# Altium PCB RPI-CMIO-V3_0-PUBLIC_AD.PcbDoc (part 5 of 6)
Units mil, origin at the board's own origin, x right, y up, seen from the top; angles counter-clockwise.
Board outline 3295.4 x 4105.44 mil, 6 copper layers (TOP, GNDT, PWRT, PWRB, GNDB, BOTTOM); 114 components, 152 nets, 703 pads, 476 vias.
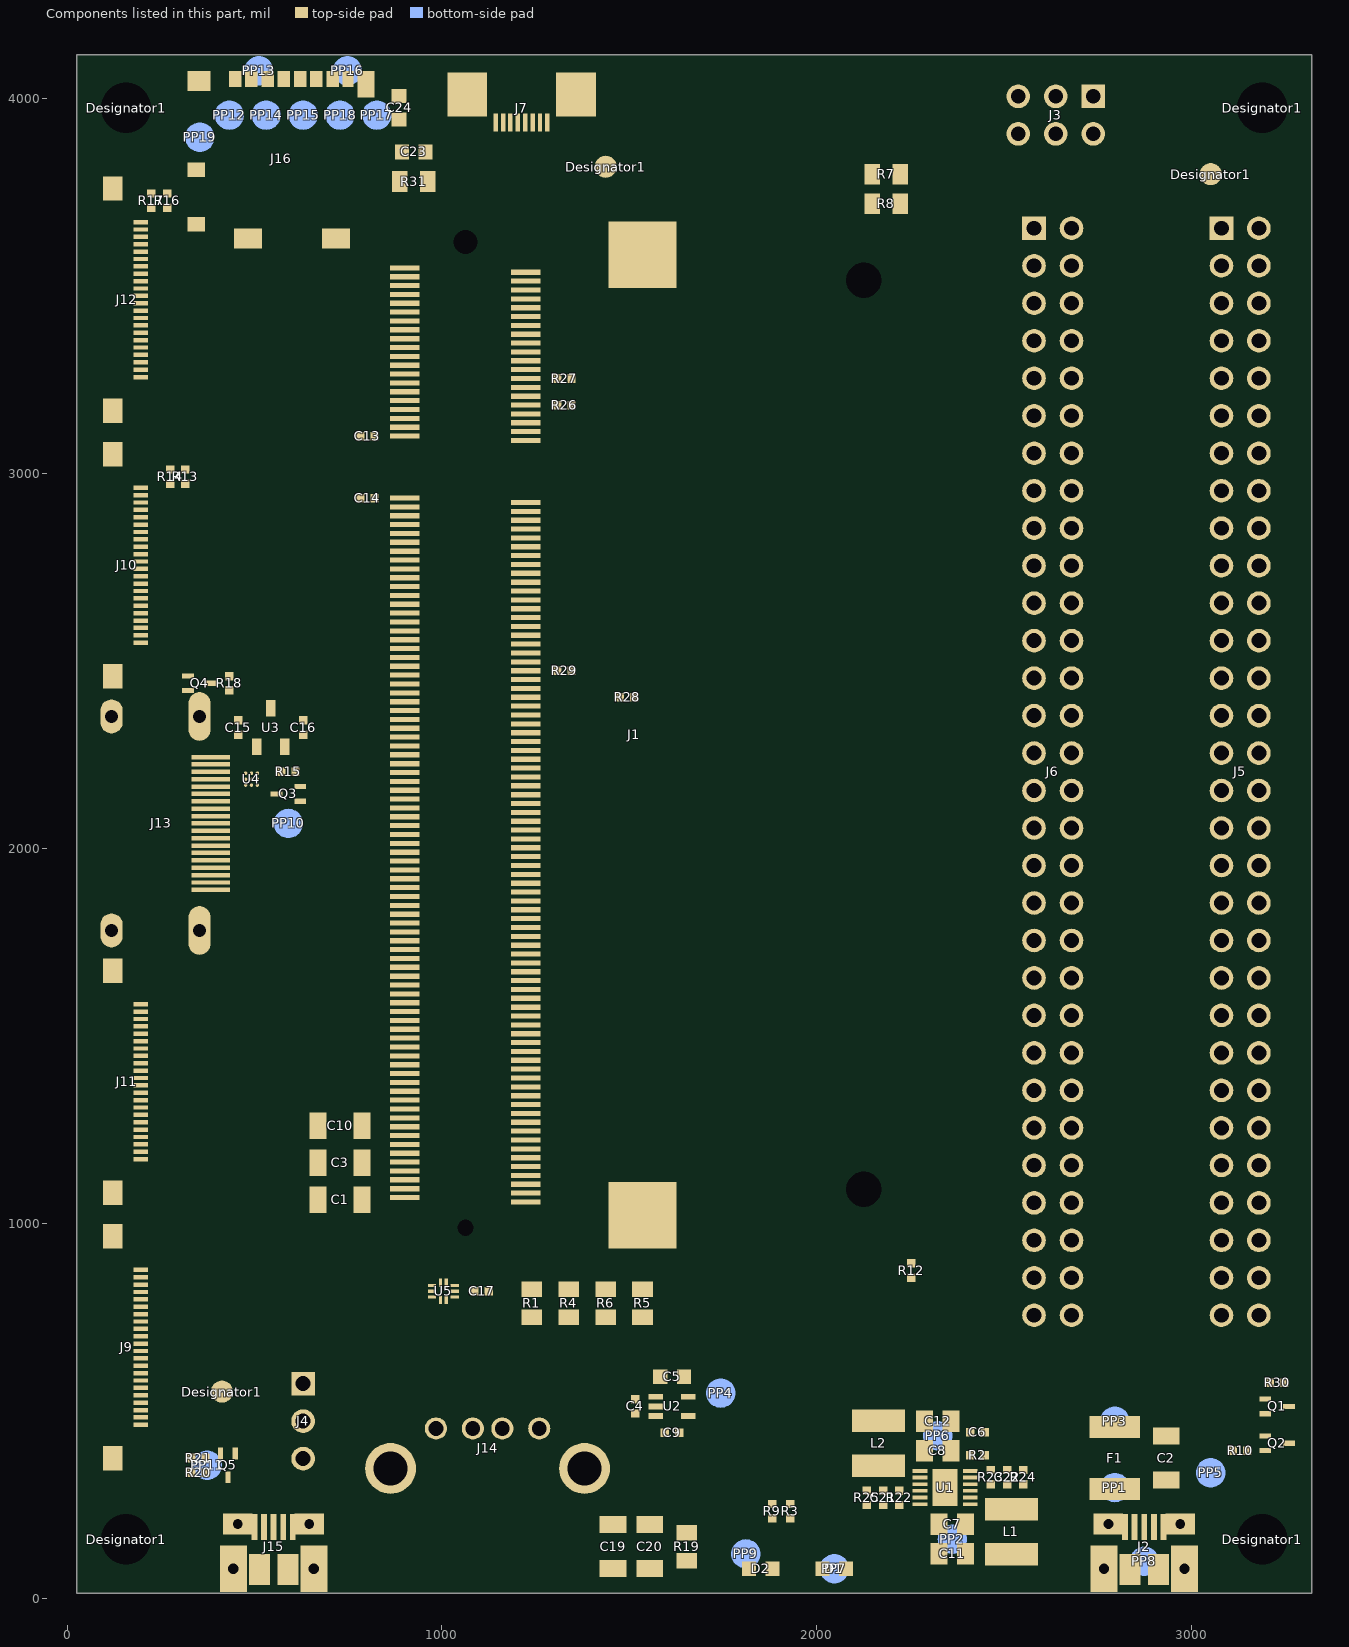
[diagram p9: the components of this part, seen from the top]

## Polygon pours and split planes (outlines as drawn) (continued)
GND on TOP "TOP-GND 73" (solid, pour order 1101): 857.11,3261.57 ccw(c852.93,3265.75) 857.11,3269.92 854.32,3272.71 845.89,3265.75 854.32,3258.79 857.11,3261.57 ccw(c852.93,3265.75)
GND on TOP "TOP-GND 74" (solid, pour order 1102): 857.11,3332.44 ccw(c852.93,3336.61) 857.11,3340.79 854.32,3343.57 845.89,3336.61 854.32,3329.66 857.11,3332.44 ccw(c852.93,3336.61)
GND on TOP "TOP-GND 75" (solid, pour order 1103): 857.11,3403.3 ccw(c852.93,3407.48) 857.11,3411.66 854.32,3414.44 845.89,3407.48 854.32,3400.52 857.11,3403.3 ccw(c852.93,3407.48)
GND on TOP "TOP-GND 76" (solid, pour order 1104): 857.11,3474.17 ccw(c852.93,3478.35) 857.11,3482.52 854.32,3485.3 845.89,3478.35 854.32,3471.39 857.11,3474.17 ccw(c852.93,3478.35)
GND on TOP "TOP-GND 77" (solid, pour order 1105): 1179.94,1100.15 ccw(c1175.76,1104.33) 1179.94,1108.51 1177.15,1111.29 1168.72,1104.33 1177.15,1097.37 1179.94,1100.15 ccw(c1175.76,1104.33)
GND on TOP "TOP-GND 78" (solid, pour order 1106): 1268.88,1273.86 ccw(c1273.05,1269.68) 1268.88,1265.51 1271.66,1262.73 1280.1,1269.68 1271.66,1276.64 1268.88,1273.86 ccw(c1273.05,1269.68)
GND on TOP "TOP-GND 79" (solid, pour order 1107): 1179.94,1194.64 ccw(c1175.76,1198.82) 1179.94,1203 1177.15,1205.78 1168.72,1198.82 1177.15,1191.86 1179.94,1194.64 ccw(c1175.76,1198.82)
GND on TOP "TOP-GND 80" (solid, pour order 1108): 1268.88,1486.46 ccw(c1273.05,1482.28) 1268.88,1478.11 1271.66,1475.33 1280.1,1482.28 1271.66,1489.24 1268.88,1486.46 ccw(c1273.05,1482.28)
GND on TOP "TOP-GND 81" (solid, pour order 1109): 1268.88,1415.59 ccw(c1273.05,1411.42) 1268.88,1407.24 1271.66,1404.46 1280.1,1411.42 1271.66,1418.37 1268.88,1415.59 ccw(c1273.05,1411.42)
GND on TOP "TOP-GND 82" (solid, pour order 1110): 1268.88,1699.06 ccw(c1273.05,1694.88) 1268.88,1690.7 1271.66,1687.93 1280.1,1694.88 1271.66,1701.84 1268.88,1699.06 ccw(c1273.05,1694.88)
GND on TOP "TOP-GND 83" (solid, pour order 1111): 1268.88,1628.19 ccw(c1273.05,1624.02) 1268.88,1619.84 1271.66,1617.06 1280.1,1624.02 1271.66,1630.97 1268.88,1628.19 ccw(c1273.05,1624.02)
GND on TOP "TOP-GND 84" (solid, pour order 1112): 1268.88,1840.79 ccw(c1273.05,1836.61) 1268.88,1832.44 1271.66,1829.66 1280.1,1836.61 1271.66,1843.57 1268.88,1840.79 ccw(c1273.05,1836.61)
GND on TOP "TOP-GND 85" (solid, pour order 1113): 1268.88,1769.93 ccw(c1273.05,1765.75) 1268.88,1761.57 1271.66,1758.79 1280.1,1765.75 1271.66,1772.7 1268.88,1769.93 ccw(c1273.05,1765.75)
GND on TOP "TOP-GND 86" (solid, pour order 1114): 1268.88,2053.39 ccw(c1273.05,2049.21) 1268.88,2045.03 1271.66,2042.26 1280.1,2049.21 1271.66,2056.17 1268.88,2053.39 ccw(c1273.05,2049.21)
GND on TOP "TOP-GND 87" (solid, pour order 1115): 1268.88,1982.52 ccw(c1273.05,1978.35) 1268.88,1974.17 1271.66,1971.39 1280.1,1978.35 1271.66,1985.3 1268.88,1982.52 ccw(c1273.05,1978.35)
GND on TOP "TOP-GND 88" (solid, pour order 1116): 1268.88,2195.12 ccw(c1273.05,2190.95) 1268.88,2186.77 1271.66,2183.99 1280.1,2190.95 1271.66,2197.9 1268.88,2195.12 ccw(c1273.05,2190.95)
GND on TOP "TOP-GND 89" (solid, pour order 1117): 1268.88,2124.26 ccw(c1273.05,2120.08) 1268.88,2115.9 1271.66,2113.12 1280.1,2120.08 1271.66,2127.03 1268.88,2124.26 ccw(c1273.05,2120.08)
GND on TOP "TOP-GND 90" (solid, pour order 1118): 1268.88,2407.72 ccw(c1273.05,2403.54) 1268.88,2399.37 1271.66,2396.59 1280.1,2403.54 1271.66,2410.5 1268.88,2407.72 ccw(c1273.05,2403.54)
GND on TOP "TOP-GND 91" (solid, pour order 1119): 1268.88,2336.85 ccw(c1273.05,2332.68) 1268.88,2328.5 1271.66,2325.72 1280.1,2332.68 1271.66,2339.63 1268.88,2336.85 ccw(c1273.05,2332.68)
GND on TOP "TOP-GND 92" (solid, pour order 1120): 1268.88,2265.99 ccw(c1273.05,2261.81) 1268.88,2257.63 1271.66,2254.85 1280.1,2261.81 1271.66,2268.77 1268.88,2265.99 ccw(c1273.05,2261.81)
GND on TOP "TOP-GND 93" (solid, pour order 1121): 1268.88,2549.45 ccw(c1273.05,2545.28) 1268.88,2541.1 1271.66,2538.32 1280.1,2545.28 1271.66,2552.23 1268.88,2549.45 ccw(c1273.05,2545.28)
GND on TOP "TOP-GND 94" (solid, pour order 1122): 1268.88,2478.59 ccw(c1273.05,2474.41) 1268.88,2470.23 1271.66,2467.45 1280.1,2474.41 1271.66,2481.37 1268.88,2478.59 ccw(c1273.05,2474.41)
GND on TOP "TOP-GND 95" (solid, pour order 1123): 1289.76,2471.63 ccw(c1286.97,2474.41) 1289.76,2477.19 1285.58,2481.37 1277.64,2474.41 1285.58,2467.45 1289.76,2471.63 ccw(c1286.97,2474.41)
GND on TOP "TOP-GND 96" (solid, pour order 1124): 1268.88,2620.32 ccw(c1273.05,2616.14) 1268.88,2611.97 1271.66,2609.18 1280.1,2616.14 1271.66,2623.1 1268.88,2620.32 ccw(c1273.05,2616.14)
GND on TOP "TOP-GND 97" (solid, pour order 1125): 1268.88,2762.05 ccw(c1273.05,2757.87) 1268.88,2753.7 1271.66,2750.92 1280.1,2757.87 1271.66,2764.83 1268.88,2762.05 ccw(c1273.05,2757.87)
GND on TOP "TOP-GND 98" (solid, pour order 1126): 1268.88,2691.18 ccw(c1273.05,2687.01) 1268.88,2682.83 1271.66,2680.05 1280.1,2687.01 1271.66,2693.97 1268.88,2691.18 ccw(c1273.05,2687.01)
GND on TOP "TOP-GND 99" (solid, pour order 1127): 1268.88,2903.78 ccw(c1273.05,2899.61) 1268.88,2895.43 1271.66,2892.65 1280.1,2899.61 1271.66,2906.56 1268.88,2903.78 ccw(c1273.05,2899.61)
GND on TOP "TOP-GND 100" (solid, pour order 1128): 1268.88,2832.92 ccw(c1273.05,2828.74) 1268.88,2824.56 1271.66,2821.78 1280.1,2828.74 1271.66,2835.7 1268.88,2832.92 ccw(c1273.05,2828.74)
GND on TOP "TOP-GND 101" (solid, pour order 1129): 1268.88,3116.38 ccw(c1273.05,3112.21) 1268.88,3108.03 1271.66,3105.25 1280.1,3112.21 1271.66,3119.16 1268.88,3116.38 ccw(c1273.05,3112.21)
GND on TOP "TOP-GND 102" (solid, pour order 1130): 1268.88,3258.11 ccw(c1273.05,3253.94) 1268.88,3249.76 1271.66,3246.98 1280.1,3253.94 1271.66,3260.89 1268.88,3258.11 ccw(c1273.05,3253.94)
GND on TOP "TOP-GND 103" (solid, pour order 1131): 1268.88,3187.25 ccw(c1273.05,3183.07) 1268.88,3178.89 1271.66,3176.11 1280.1,3183.07 1271.66,3190.03 1268.88,3187.25 ccw(c1273.05,3183.07)
GND on TOP "TOP-GND 104" (solid, pour order 1132): 1289.76,3180.29 ccw(c1286.97,3183.07) 1289.76,3185.85 1285.58,3190.03 1277.64,3183.07 1285.58,3176.11 1289.76,3180.29 ccw(c1286.97,3183.07)
GND on TOP "TOP-GND 105" (solid, pour order 1133): 1595.65,515.99 ccw(c1599.83,511.81) 1595.65,507.63 1598.44,504.85 1606.87,511.81 1598.44,518.77 1595.65,515.99 ccw(c1599.83,511.81)
GND on TOP "TOP-GND 106" (solid, pour order 1134): 1558.88,586.37 ccw(c1554.7,590.55) 1558.88,594.73 1556.09,597.51 1547.66,590.55 1556.09,583.6 1558.88,586.37 ccw(c1554.7,590.55)
GND on TOP "TOP-GND 107" (solid, pour order 1135): 1544.68,2407.48 ccw(c1544.8,2403.55) 1542.02,2400.76 1550.13,2392.65 1558.02,2399.31 1552.79,2407.72 1544.68,2407.48 ccw(c1544.8,2403.55)
GND on TOP "TOP-GND 108" (solid, pour order 1136): 1991.95,74.56 ccw(c1987.77,78.74) 1991.95,82.92 1989.16,85.7 1980.73,78.74 1989.16,71.78 1991.95,74.56 ccw(c1987.77,78.74)
GND on TOP "TOP-GND 109" (solid, pour order 1137): 2136.64,233.89 ccw(c2133.86,231.11) 2131.08,233.89 2126.9,229.72 2133.86,221.77 2140.82,229.72 2136.64,233.89 ccw(c2133.86,231.11)
GND on TOP "TOP-GND 110" (solid, pour order 1138): 2254.75,840.19 ccw(c2251.97,837.41) 2249.18,840.19 2245.01,836.02 2251.97,828.07 2258.93,836.02 2254.75,840.19 ccw(c2251.97,837.41)
GND on TOP "TOP-GND 111" (solid, pour order 1139): 2548.4,356.66 ccw(c2551.18,359.44) 2553.97,356.66 2558.14,360.84 2551.18,368.78 2544.22,360.84 2548.4,356.66 ccw(c2551.18,359.44)
GND on TOP "TOP-GND 112" (solid, pour order 1140): 2444.07,458.83 ccw(c2446.85,461.61) 2449.63,458.83 2453.81,463 2446.85,470.94 2439.89,463 2444.07,458.83 ccw(c2446.85,461.61)
GND on TOP "TOP-GND 113" (solid, pour order 1141): 3216.31,396.48 ccw(c3219.09,393.7) 3216.31,390.92 3220.48,386.74 3228.42,393.7 3220.48,400.66 3216.31,396.48 ccw(c3219.09,393.7)
GND on TOP "TOP-GND 114" (solid, pour order 1142): 2316.93,346.46 2316.93,523.62 2381.89,523.62 2381.89,346.46 2377.95,346.46 2377.95,244.09 2368.11,244.09 2368.11,88.58 2303.15,88.58 2303.15,226.38 2307.09,226.38 2307.09,346.46
GND on TOP "TOP-GND 115" (solid, pour order 1143): 567 vertices, not listed, extent 19.68,19.68 3326.77,4114.17
GND on TOP "TOP-GND 116" (solid, pour order 1144): 1325.91,2410.94 ccw(c1338.59,2401.58) 1322.83,2401.58 1322.83,2399.75 1312.85,2389.77 1269.69,2389.77 1269.69,2417.32 1322.69,2417.32 cw(c1322.69,2413.32) 1325.91,2410.94 ccw(c1338.59,2401.58)
GND on TOP "TOP-GND 117" (solid, pour order 1145): 440.56,2194.89 440.56,2234.24 443.44,2234.24 460.62,2217.06 460.62,2207.55 465.91,2202.26 465.85,2201.37 ccw(c476.38,2200.79) 465.93,2199.41 cw(c461.96,2198.89) 461.97,2194.89
GND on TOP "TOP-GND 118" (solid, pour order 1146): 946.86,1238.74 cw(c950.86,1238.74) 951.85,1242.62 ccw(c955.79,1257.87) 961.37,1243.14 cw(c962.78,1239.4) 966.78,1239.4 966.78,1181.86 cw(c962.78,1181.86) 961.37,1178.12 ccw(c955.79,1163.39) 951.85,1178.64 cw(c950.86,1182.52) 946.86,1182.52 946.86,1238.74 cw(c950.86,1238.74)
GND on TOP "TOP-GND 119" (solid, pour order 1147): 946.86,1144.26 cw(c950.86,1144.26) 951.85,1148.13 ccw(c955.79,1163.39) 961.37,1148.65 cw(c962.78,1144.91) 966.78,1144.91 966.78,1087.37 cw(c962.78,1087.37) 961.37,1083.63 ccw(c955.79,1068.9) 951.85,1084.15 cw(c950.86,1088.03) 946.86,1088.03 946.86,1144.26 cw(c950.86,1144.26)
GPIO7 on TOP "TOP-GPIO7" (solid, pour order 1148): 961.31,3292.15 ccw(c964.09,3289.37) 961.31,3286.59 965.48,3282.41 973.42,3289.37 965.48,3296.33 961.31,3292.15 ccw(c964.09,3289.37)
1V8 on TOP "TOP-1V8" (solid, pour order 1149): 397.64,2470.2 ccw(c397.64,2474.13) 401.58,2474.13 401.58,2480.04 391.04,2480.74 391.73,2470.2 397.64,2470.2 ccw(c397.64,2474.13)
1V8 on TOP "TOP-1V8 1" (solid, pour order 1150): 2297.24,519.76 ccw(c2291.34,519.76) 2291.34,525.67 2287.4,525.67 2286.36,514.78 2297.24,515.83 2297.24,519.76 ccw(c2291.34,519.76)
1V8 on TOP "TOP-1V8 2" (solid, pour order 1151): 3151.6,377.79 ccw(c3148.82,375) 3146.04,377.79 3141.86,373.61 3148.82,365.67 3155.78,373.61 3151.6,377.79 ccw(c3148.82,375)
GPIO26 on TOP "TOP-GPIO26" (solid, pour order 1152): 1105.01,2394.52 ccw(c1107.79,2391.73) 1105.01,2388.95 1109.18,2384.78 1117.13,2391.73 1109.18,2398.69 1105.01,2394.52 ccw(c1107.79,2391.73)
3V3 on TOP "TOP-3V3" (solid, pour order 1153): 173.46,873.2 ccw(c170.67,875.98) 173.46,878.77 169.28,882.94 161.34,875.98 169.28,869.03 173.46,873.2 ccw(c170.67,875.98)
3V3 on TOP "TOP-3V3 1" (solid, pour order 1154): 220.24,1587.43 ccw(c223.03,1584.65) 220.24,1581.86 224.42,1577.69 232.36,1584.65 224.42,1591.6 220.24,1587.43 ccw(c223.03,1584.65)
3V3 on TOP "TOP-3V3 2" (solid, pour order 1155): 173.46,2959.82 ccw(c170.67,2962.6) 173.46,2965.38 169.28,2969.55 161.34,2962.6 169.28,2955.64 173.46,2959.82 ccw(c170.67,2962.6)
3V3 on TOP "TOP-3V3 3" (solid, pour order 1156): 173.46,3668.48 ccw(c170.67,3671.26) 173.46,3674.04 169.28,3678.22 161.34,3671.26 169.28,3664.3 173.46,3668.48 ccw(c170.67,3671.26)
3V3 on TOP "TOP-3V3 4" (solid, pour order 1157): 316.57,331.86 ccw(c313.78,334.65) 316.57,337.43 312.39,341.6 304.45,334.65 312.39,327.69 316.57,331.86 ccw(c313.78,334.65)
3V3 on TOP "TOP-3V3 5" (solid, pour order 1158): 272.81,3025.95 ccw(c275.59,3028.74) 278.37,3025.95 282.55,3030.13 275.59,3038.07 268.63,3030.13 272.81,3025.95 ccw(c275.59,3028.74)
3V3 on TOP "TOP-3V3 6" (solid, pour order 1159): 312.18,3026.27 ccw(c314.96,3029.05) 317.74,3026.27 321.92,3030.44 314.96,3038.39 308,3030.44 312.18,3026.27 ccw(c314.96,3029.05)
3V3 on TOP "TOP-3V3 7" (solid, pour order 1160): 624.38,2207.51 ccw(c627.16,2204.72) 624.38,2201.94 628.55,2197.77 636.5,2204.72 628.55,2211.68 624.38,2207.51 ccw(c627.16,2204.72)
3V3 on TOP "TOP-3V3 8" (solid, pour order 1161): 1091.37,802.08 ccw(c1088.58,799.3) 1085.8,802.08 1081.63,797.9 1088.58,789.96 1095.54,797.9 1091.37,802.08 ccw(c1088.58,799.3)
3V3 on TOP "TOP-3V3 9" (solid, pour order 1162): 1595.65,490.4 ccw(c1599.83,486.22) 1595.65,482.04 1598.44,479.26 1606.87,486.22 1598.44,493.18 1595.65,490.4 ccw(c1599.83,486.22)
3V3 on TOP "TOP-3V3 10" (solid, pour order 1163): 1595.65,541.58 ccw(c1599.83,537.4) 1595.65,533.22 1598.44,530.44 1606.87,537.4 1598.44,544.36 1595.65,541.58 ccw(c1599.83,537.4)
3V3 on TOP "TOP-3V3 11" (solid, pour order 1164): 1877.71,265.85 ccw(c1881.89,270.02) 1886.07,265.85 1888.85,268.63 1881.89,277.07 1874.93,268.63 1877.71,265.85 ccw(c1881.89,270.02)
3V3 on TOP "TOP-3V3 12" (solid, pour order 1165): 1924.96,265.85 ccw(c1929.13,270.02) 1933.31,265.85 1936.09,268.63 1929.13,277.07 1922.18,268.63 1924.96,265.85 ccw(c1929.13,270.02)
3V3 on TOP "TOP-3V3 13" (solid, pour order 1166): 2387.89,78.9 ccw(c2392.07,74.72) 2387.89,70.55 2390.68,67.77 2399.11,74.72 2390.68,81.68 2387.89,78.9 ccw(c2392.07,74.72)
GPIO4 on TOP "TOP-GPIO4" (solid, pour order 1167): 980.99,3386.64 ccw(c983.78,3383.86) 980.99,3381.08 985.16,3376.9 993.11,3383.86 985.16,3390.82 980.99,3386.64 ccw(c983.78,3383.86)
GPIO24 on TOP "TOP-GPIO24" (solid, pour order 1168): 1126.66,2465.38 ccw(c1129.45,2462.6) 1126.66,2459.82 1130.84,2455.64 1138.78,2462.6 1130.84,2469.55 1126.66,2465.38 ccw(c1129.45,2462.6)
GPIO28-45_VREF on TOP "TOP-GPIO28-45_VREF" (solid, pour order 1169): 946.04,2939.22 ccw(c950.22,2935.04) 946.04,2930.86 948.83,2928.08 957.26,2935.04 948.83,2942 946.04,2939.22 ccw(c950.22,2935.04)
GPIO28-45_VREF on TOP "TOP-GPIO28-45_VREF 1" (solid, pour order 1170): 1179.94,2919.05 ccw(c1175.76,2923.23) 1179.94,2927.41 1177.15,2930.18 1168.72,2923.23 1177.15,2916.27 1179.94,2919.05 ccw(c1175.76,2923.23)
VC_TRST_N on TOP "TOP-VC_TRST_N" (solid, pour order 1171): 1504.61,1390.58 ccw(c1507.4,1387.8) 1504.61,1385.01 1508.79,1380.84 1516.73,1387.8 1508.79,1394.75 1504.61,1390.58 ccw(c1507.4,1387.8)
CAM0_CN on TOP "TOP-CAM0_CN" (solid, pour order 1172): 147.79,592.54 ccw(c146.17,594.15) 147.79,595.77 142.44,601.11 134.91,594.15 142.44,587.2 147.79,592.54 ccw(c146.17,594.15)
CAM0_CN on TOP "TOP-CAM0_CN 1" (solid, pour order 1173): 1313.9,1724.63 ccw(c1313.9,1722.35) 1311.61,1722.35 1311.61,1714.79 1321.86,1714.39 1321.46,1724.63 1313.9,1724.63 ccw(c1313.9,1722.35)
GPIO2 on TOP "TOP-GPIO2" (solid, pour order 1174): 944.65,3457.51 ccw(c947.44,3454.72) 944.65,3451.94 948.83,3447.77 956.77,3454.72 948.83,3461.68 944.65,3457.51 ccw(c947.44,3454.72)
DSI1_DN3 on TOP "TOP-DSI1_DN3" (solid, pour order 1175): 252.82,3518.63 ccw(c252.82,3516.35) 250.54,3516.35 250.54,3508.79 260.78,3508.39 260.38,3518.63 252.82,3518.63 ccw(c252.82,3516.35)
DSI1_DN3 on TOP "TOP-DSI1_DN3 1" (solid, pour order 1176): 1313.64,2149.85 ccw(c1313.64,2147.59) 1311.38,2147.59 1311.38,2140.01 1321.62,2139.61 1321.22,2149.85 1313.64,2149.85 ccw(c1313.64,2147.59)
GPIO20 on TOP "TOP-GPIO20" (solid, pour order 1177): 967.21,2607.11 ccw(c970,2604.33) 967.21,2601.55 971.39,2597.37 979.33,2604.33 971.39,2611.29 967.21,2607.11 ccw(c970,2604.33)
GPIO8 on TOP "TOP-GPIO8" (solid, pour order 1178): 975.09,3244.91 ccw(c977.87,3242.13) 975.09,3239.34 979.26,3235.17 987.21,3242.13 979.26,3249.08 975.09,3244.91 ccw(c977.87,3242.13)
DSI1_DN2 on TOP "TOP-DSI1_DN2" (solid, pour order 1179): 266.76,3457.85 ccw(c266.76,3455.57) 264.48,3455.57 264.48,3448.01 274.72,3447.61 274.32,3457.85 266.76,3457.85 ccw(c266.76,3455.57)
DSI1_DN2 on TOP "TOP-DSI1_DN2 1" (solid, pour order 1180): 1313.68,2078.84 ccw(c1313.68,2076.58) 1311.42,2076.58 1311.42,2069 1321.66,2068.6 1321.26,2078.84 1313.68,2078.84 ccw(c1313.68,2076.58)
DSI0_DP1 on TOP "TOP-DSI0_DP1" (solid, pour order 1181): 289.45,2511.87 ccw(c287.84,2510.25) 286.22,2511.87 280.88,2506.52 287.84,2498.99 294.8,2506.52 289.45,2511.87 ccw(c287.84,2510.25)
DSI0_DP1 on TOP "TOP-DSI0_DP1 1" (solid, pour order 1182): 750,2300.06 ccw(c747.72,2300.06) 747.72,2302.34 740.16,2302.34 739.75,2292.1 750,2292.5 750,2300.06 ccw(c747.72,2300.06)
VC_TDO on TOP "TOP-VC_TDO" (solid, pour order 1183): 1453.43,1319.71 ccw(c1456.22,1316.93) 1453.43,1314.15 1457.61,1309.97 1465.55,1316.93 1457.61,1323.89 1453.43,1319.71 ccw(c1456.22,1316.93)
GPIO15 on TOP "TOP-GPIO15" (solid, pour order 1184): 951.47,2796.09 ccw(c954.25,2793.31) 951.47,2790.52 955.64,2786.35 963.58,2793.31 955.64,2800.26 951.47,2796.09 ccw(c954.25,2793.31)
GPIO25 on TOP "TOP-GPIO25" (solid, pour order 1185): 1097.13,2441.76 ccw(c1099.92,2438.98) 1097.13,2436.19 1101.31,2432.02 1109.25,2438.98 1101.31,2445.93 1097.13,2441.76 ccw(c1099.92,2438.98)
DSI1_DN0 on TOP "TOP-DSI1_DN0" (solid, pour order 1186): 590.87,3280.69 ccw(c590.87,3278.41) 588.58,3278.41 588.58,3270.85 598.83,3270.44 598.42,3280.69 590.87,3280.69 ccw(c590.87,3278.41)
DSI1_DN0 on TOP "TOP-DSI1_DN0 1" (solid, pour order 1187): 1313.64,2291.59 ccw(c1313.64,2289.32) 1311.38,2289.32 1311.38,2281.74 1321.62,2281.34 1321.22,2291.59 1313.64,2291.59 ccw(c1313.64,2289.32)
GPIO17 on TOP "TOP-GPIO17" (solid, pour order 1188): 944.65,2725.22 ccw(c947.44,2722.44) 944.65,2719.66 948.83,2715.48 956.77,2722.44 948.83,2729.4 944.65,2725.22 ccw(c947.44,2722.44)
GPIO11 on TOP "TOP-GPIO11" (solid, pour order 1189): 944.65,3150.42 ccw(c947.44,3147.64) 944.65,3144.85 948.83,3140.68 956.77,3147.64 948.83,3154.59 944.65,3150.42 ccw(c947.44,3147.64)
GPIO22 on TOP "TOP-GPIO22" (solid, pour order 1190): 1022.33,2536.25 ccw(c1025.11,2533.47) 1022.33,2530.68 1026.5,2526.51 1034.45,2533.47 1026.5,2540.42 1022.33,2536.25 ccw(c1025.11,2533.47)
CD1_SCL on TOP "TOP-CD1_SCL" (solid, pour order 1191): 174.52,1542.49 ccw(c171.74,1545.28) 174.52,1548.06 170.35,1552.23 162.4,1545.28 170.35,1538.32 174.52,1542.49 ccw(c171.74,1545.28)
CD1_SCL on TOP "TOP-CD1_SCL 1" (solid, pour order 1192): 173.46,3629.11 ccw(c170.67,3631.89) 173.46,3634.67 169.28,3638.85 161.34,3631.89 169.28,3624.93 173.46,3629.11 ccw(c170.67,3631.89)
HDMI_CEC on TOP "TOP-HDMI_CEC" (solid, pour order 1193): 648.32,2168.14 ccw(c651.1,2165.35) 648.32,2162.57 652.49,2158.4 660.43,2165.35 652.49,2172.31 648.32,2168.14 ccw(c651.1,2165.35)
HDMI_CEC on TOP "TOP-HDMI_CEC 1" (solid, pour order 1194): 822.16,1396.82 ccw(c819.37,1399.61) 822.16,1402.39 817.98,1406.56 810.04,1399.61 817.98,1392.65 822.16,1396.82 ccw(c819.37,1399.61)
CAM1_IO0 on TOP "TOP-CAM1_IO0" (solid, pour order 1195): 250.68,1489 ccw(c253.46,1486.22) 250.68,1483.44 254.85,1479.26 262.8,1486.22 254.85,1493.18 250.68,1489 ccw(c253.46,1486.22)
CD1_SDA on TOP "TOP-CD1_SDA" (solid, pour order 1196): 144.99,1562.18 ccw(c142.21,1564.96) 144.99,1567.74 140.82,1571.92 132.87,1564.96 140.82,1558 144.99,1562.18 ccw(c142.21,1564.96)
CD1_SDA on TOP "TOP-CD1_SDA 1" (solid, pour order 1197): 150.9,3648.79 ccw(c148.11,3651.58) 150.9,3654.36 146.72,3658.53 138.78,3651.58 146.72,3644.62 150.9,3648.79 ccw(c148.11,3651.58)
DSI1_CP on TOP "TOP-DSI1_CP" (solid, pour order 1198): 496.06,3414.51 ccw(c498.35,3414.51) 498.35,3412.22 505.91,3412.22 506.31,3422.47 496.06,3422.07 496.06,3414.51 ccw(c498.35,3414.51)
DSI1_CP on TOP "TOP-DSI1_CP 1" (solid, pour order 1199): 1311.42,2234.15 ccw(c1313.68,2234.15) 1313.68,2231.89 1321.26,2231.89 1321.66,2242.13 1311.42,2241.73 1311.42,2234.15 ccw(c1313.68,2234.15)
CAM1_IO1 on TOP "TOP-CAM1_IO1" (solid, pour order 1200): 170.58,1503.12 ccw(c167.8,1505.91) 170.58,1508.69 166.41,1512.86 158.47,1505.91 166.41,1498.95 170.58,1503.12 ccw(c167.8,1505.91)
VDD_CORE on TOP "TOP-VDD_CORE" (solid, pour order 1201): 960.63,1301.18 ccw(c960.63,1297.24) 956.69,1297.24 956.69,1291.34 967.23,1290.64 966.54,1301.18 960.63,1301.18 ccw(c960.63,1297.24)
VDD_CORE on TOP "TOP-VDD_CORE 1" (solid, pour order 1202): 2044.6,1302.34 ccw(c2041.82,1305.12) 2044.6,1307.9 2040.43,1312.08 2032.48,1305.12 2040.43,1298.16 2044.6,1302.34 ccw(c2041.82,1305.12)
GPIO16 on TOP "TOP-GPIO16" (solid, pour order 1203): 973.12,2748.85 ccw(c975.9,2746.06) 973.12,2743.28 977.29,2739.11 985.24,2746.06 977.29,2753.02 973.12,2748.85 ccw(c975.9,2746.06)
DSI0_CP on TOP "TOP-DSI0_CP" (solid, pour order 1204): 127.91,2703.56 ccw(c127.91,2705.85) 130.19,2705.85 130.19,2713.41 119.94,2713.81 120.35,2703.56 127.91,2703.56 ccw(c127.91,2705.85)
DSI0_CP on TOP "TOP-DSI0_CP 1" (solid, pour order 1205): 689.87,2392.66 ccw(c691.49,2394.28) 693.1,2392.66 698.44,2398.01 691.49,2405.54 684.53,2398.01 689.87,2392.66 ccw(c691.49,2394.28)
GPIO14 on TOP "TOP-GPIO14" (solid, pour order 1206): 975.09,2819.71 ccw(c977.87,2816.93) 975.09,2814.15 979.26,2809.97 987.21,2816.93 979.26,2823.89 975.09,2819.71 ccw(c977.87,2816.93)
RUN on TOP "TOP-RUN" (solid, pour order 1207): 944.65,1331.52 ccw(c947.44,1328.74) 944.65,1325.96 948.83,1321.78 956.77,1328.74 948.83,1335.7 944.65,1331.52 ccw(c947.44,1328.74)
VC_TMS on TOP "TOP-VC_TMS" (solid, pour order 1208): 1421.94,1343.34 ccw(c1424.72,1340.55) 1421.94,1337.77 1426.11,1333.59 1434.05,1340.55 1426.11,1347.51 1421.94,1343.34 ccw(c1424.72,1340.55)
VC_TCK on TOP "TOP-VC_TCK" (solid, pour order 1209): 1396.49,1296.09 ccw(c1399.27,1293.31) 1396.49,1290.52 1400.66,1286.35 1408.61,1293.31 1400.66,1300.26 1396.49,1296.09 ccw(c1399.27,1293.31)
VC_TDI on TOP "TOP-VC_TDI" (solid, pour order 1210): 1480.99,1366.96 ccw(c1483.78,1364.17) 1480.99,1361.39 1485.16,1357.22 1493.11,1364.17 1485.16,1371.13 1480.99,1366.96 ccw(c1483.78,1364.17)
DSI1_DP1 on TOP "TOP-DSI1_DP1" (solid, pour order 1211): 264.48,3355.45 ccw(c266.76,3355.45) 266.76,3353.17 274.32,3353.17 274.72,3363.42 264.48,3363.01 264.48,3355.45 ccw(c266.76,3355.45)
DSI1_DP1 on TOP "TOP-DSI1_DP1 1" (solid, pour order 1212): 1311.38,2021.7 ccw(c1313.64,2021.7) 1313.64,2019.44 1321.22,2019.44 1321.62,2029.68 1311.38,2029.28 1311.38,2021.7 ccw(c1313.64,2021.7)
DSI1_DP3 on TOP "TOP-DSI1_DP3" (solid, pour order 1213): 250.54,3534.35 ccw(c252.82,3534.35) 252.82,3532.06 260.38,3532.06 260.78,3542.31 250.54,3541.91 250.54,3534.35 ccw(c252.82,3534.35)
DSI1_DP3 on TOP "TOP-DSI1_DP3 1" (solid, pour order 1214): 1311.38,2163.43 ccw(c1313.64,2163.43) 1313.64,2161.17 1321.22,2161.17 1321.62,2171.41 1311.38,2171.01 1311.38,2163.43 ccw(c1313.64,2163.43)
GPIO9 on TOP "TOP-GPIO9" (solid, pour order 1215): 951.47,3221.29 ccw(c954.25,3218.5) 951.47,3215.72 955.64,3211.55 963.58,3218.5 955.64,3225.46 951.47,3221.29 ccw(c954.25,3218.5)
CAM0_CP on TOP "TOP-CAM0_CP" (solid, pour order 1216): 147.79,623.58 ccw(c146.17,625.2) 147.79,626.81 142.44,632.15 134.91,625.2 142.44,618.24 147.79,623.58 ccw(c146.17,625.2)
CAM0_CP on TOP "TOP-CAM0_CP 1" (solid, pour order 1217): 1311.61,1738.28 ccw(c1313.9,1738.28) 1313.9,1735.99 1321.46,1735.99 1321.86,1746.24 1311.61,1745.84 1311.61,1738.28 ccw(c1313.9,1738.28)
GPIO0 on TOP "TOP-GPIO0" (solid, pour order 1218): 944.65,3528.37 ccw(c947.44,3525.59) 944.65,3522.81 948.83,3518.63 956.77,3525.59 948.83,3532.55 944.65,3528.37 ccw(c947.44,3525.59)
GPIO3 on TOP "TOP-GPIO3" (solid, pour order 1219): 965.24,3433.89 ccw(c968.03,3431.1) 965.24,3428.32 969.42,3424.15 977.36,3431.1 969.42,3438.06 965.24,3433.89 ccw(c968.03,3431.1)
GPIO1 on TOP "TOP-GPIO1" (solid, pour order 1220): 965.24,3504.75 ccw(c968.03,3501.97) 965.24,3499.18 969.42,3495.01 977.36,3501.97 969.42,3508.92 965.24,3504.75 ccw(c968.03,3501.97)
CEC on TOP "TOP-CEC" (solid, pour order 1221): 328.58,2123.2 ccw(c325.79,2125.98) 328.58,2128.77 324.4,2132.94 316.46,2125.98 324.4,2119.03 328.58,2123.2 ccw(c325.79,2125.98)
CAM0_DN1 on TOP "TOP-CAM0_DN1" (solid, pour order 1222): 147.79,533.48 ccw(c146.17,535.1) 147.79,536.71 142.44,542.06 134.91,535.1 142.44,528.14 147.79,533.48 ccw(c146.17,535.1)
CAM0_DN1 on TOP "TOP-CAM0_DN1 1" (solid, pour order 1223): 1313.9,1653.77 ccw(c1313.9,1651.48) 1311.61,1651.48 1311.61,1643.93 1321.86,1643.52 1321.46,1653.77 1313.9,1653.77 ccw(c1313.9,1651.48)
H5V on TOP "TOP-H5V" (solid, pour order 1224): 602.59,2123.2 ccw(c599.81,2125.98) 602.59,2128.77 598.42,2132.94 590.47,2125.98 598.42,2119.03 602.59,2123.2 ccw(c599.81,2125.98)
H5V on TOP "TOP-H5V 1" (solid, pour order 1225): 517.1,2203.57 ccw(c519.88,2200.79) 517.1,2198 521.27,2193.83 529.21,2200.79 521.27,2207.74 517.1,2203.57 ccw(c519.88,2200.79)
H5V on TOP "TOP-H5V 2" (solid, pour order 1226): 538.07,2204.72 ccw(c532.16,2204.72) 532.16,2210.63 528.23,2210.63 527.18,2199.74 538.07,2200.79 538.07,2204.72 ccw(c532.16,2204.72)
H5V on TOP "TOP-H5V 3" (solid, pour order 1227): 517.1,2172.08 ccw(c519.88,2169.29) 517.1,2166.51 521.27,2162.34 529.21,2169.29 521.27,2176.25 517.1,2172.08 ccw(c519.88,2169.29)
DSI1_CN on TOP "TOP-DSI1_CN" (solid, pour order 1228): 498.35,3398.79 ccw(c498.35,3396.51) 496.06,3396.51 496.06,3388.95 506.31,3388.55 505.91,3398.79 498.35,3398.79 ccw(c498.35,3396.51)
DSI1_CN on TOP "TOP-DSI1_CN 1" (solid, pour order 1229): 1313.68,2220.58 ccw(c1313.68,2218.31) 1311.42,2218.31 1311.42,2210.73 1321.66,2210.33 1321.26,2220.58 1313.68,2220.58 ccw(c1313.68,2218.31)
GPIO18 on TOP "TOP-GPIO18" (solid, pour order 1230): 975.09,2677.98 ccw(c977.87,2675.2) 975.09,2672.41 979.26,2668.24 987.21,2675.2 979.26,2682.15 975.09,2677.98 ccw(c977.87,2675.2)
DSI1_DP2 on TOP "TOP-DSI1_DP2" (solid, pour order 1231): 264.48,3473.57 ccw(c266.76,3473.57) 266.76,3471.28 274.32,3471.28 274.72,3481.53 264.48,3481.13 264.48,3473.57 ccw(c266.76,3473.57)
DSI1_DP2 on TOP "TOP-DSI1_DP2 1" (solid, pour order 1232): 1311.42,2092.42 ccw(c1313.68,2092.42) 1313.68,2090.16 1321.26,2090.16 1321.66,2100.4 1311.42,2100 1311.42,2092.42 ccw(c1313.68,2092.42)
DSI0_CN on TOP "TOP-DSI0_CN" (solid, pour order 1233): 130.19,2687.85 ccw(c127.91,2687.85) 127.91,2690.13 120.35,2690.13 119.94,2679.89 130.19,2680.29 130.19,2687.85 ccw(c127.91,2687.85)
DSI0_CN on TOP "TOP-DSI0_CN 1" (solid, pour order 1234): 702.6,2383.16 ccw(c704.22,2381.55) 702.6,2379.94 707.94,2374.6 715.48,2381.55 707.94,2388.51 702.6,2383.16 ccw(c704.22,2381.55)
GPIO21 on TOP "TOP-GPIO21" (solid, pour order 1235): 944.65,2583.49 ccw(c947.44,2580.71) 944.65,2577.93 948.83,2573.75 956.77,2580.71 948.83,2587.66 944.65,2583.49 ccw(c947.44,2580.71)
USB_OTGID on TOP "TOP-USB_OTGID" (solid, pour order 1236): 1564.96,1399.61 ccw(c1564.96,1395.67) 1561.02,1395.67 1561.02,1389.76 1571.56,1389.07 1570.87,1399.61 1564.96,1399.61 ccw(c1564.96,1395.67)
USB_OTGID on TOP "TOP-USB_OTGID 1" (solid, pour order 1237): 2187.01,1253.94 ccw(c2187.01,1257.87) 2190.95,1257.87 2190.95,1263.78 2180.41,1264.48 2181.1,1253.94 2187.01,1253.94 ccw(c2187.01,1257.87)
GPIO13 on TOP "TOP-GPIO13" (solid, pour order 1238): 951.47,2866.96 ccw(c954.25,2864.17) 951.47,2861.39 955.64,2857.22 963.58,2864.17 955.64,2871.13 951.47,2866.96 ccw(c954.25,2864.17)
CAM0_DP0 on TOP "TOP-CAM0_DP0" (solid, pour order 1239): 264.97,688.48 ccw(c266.58,690.1) 268.2,688.48 273.54,693.83 266.58,701.36 259.63,693.83 264.97,688.48 ccw(c266.58,690.1)
CAM0_DP0 on TOP "TOP-CAM0_DP0 1" (solid, pour order 1240): 1311.42,1807.4 ccw(c1313.7,1807.4) 1313.7,1805.12 1321.26,1805.12 1321.66,1815.37 1311.42,1814.96 1311.42,1807.4 ccw(c1313.7,1807.4)
GPIO0-27_VREF on TOP "TOP-GPIO0-27_VREF" (solid, pour order 1241): 946.04,3104.57 ccw(c950.22,3100.39) 946.04,3096.22 948.83,3093.44 957.26,3100.39 948.83,3107.35 946.04,3104.57 ccw(c950.22,3100.39)
GPIO0-27_VREF on TOP "TOP-GPIO0-27_VREF 1" (solid, pour order 1242): 1179.94,3084.41 ccw(c1175.76,3088.58) 1179.94,3092.76 1177.15,3095.54 1168.72,3088.58 1177.15,3081.63 1179.94,3084.41 ccw(c1175.76,3088.58)
GPIO10 on TOP "TOP-GPIO10" (solid, pour order 1243): 975.09,3174.04 ccw(c977.87,3171.26) 975.09,3168.48 979.26,3164.3 987.21,3171.26 979.26,3178.22 975.09,3174.04 ccw(c977.87,3171.26)
TVDAC on TOP "TOP-TVDAC" (solid, pour order 1244): 2537.12,756.47 ccw(c2538.86,754.72) 2537.12,752.98 2557.65,732.46 2580.53,754.72 2557.65,776.99 2537.12,756.47 ccw(c2538.86,754.72)
CM_VBAT on TOP "TOP-CM_VBAT" (solid, pour order 1245): 857.11,1088.34 ccw(c852.93,1092.52) 857.11,1096.7 854.32,1099.48 845.89,1092.52 854.32,1085.56 857.11,1088.34 ccw(c852.93,1092.52)
CM_VBAT on TOP "TOP-CM_VBAT 1" (solid, pour order 1246): 837.62,1096.7 ccw(c841.8,1092.52) 837.62,1088.34 840.4,1085.56 848.84,1092.52 840.4,1099.48 837.62,1096.7 ccw(c841.8,1092.52)
CM_VBAT on TOP "TOP-CM_VBAT 2" (solid, pour order 1247): 946.04,1073.08 ccw(c950.22,1068.9) 946.04,1064.72 948.83,1061.94 957.26,1068.9 948.83,1075.85 946.04,1073.08 ccw(c950.22,1068.9)
CM_VBAT on TOP "TOP-CM_VBAT 3" (solid, pour order 1248): 1268.88,1084.89 ccw(c1273.05,1080.71) 1268.88,1076.53 1271.66,1073.75 1280.1,1080.71 1271.66,1087.66 1268.88,1084.89 ccw(c1273.05,1080.71)
CM_VBAT on TOP "TOP-CM_VBAT 4" (solid, pour order 1249): 1179.94,1052.91 ccw(c1175.76,1057.09) 1179.94,1061.26 1177.15,1064.04 1168.72,1057.09 1177.15,1050.13 1179.94,1052.91 ccw(c1175.76,1057.09)
GPIO5 on TOP "TOP-GPIO5" (solid, pour order 1250): 959.34,3363.02 ccw(c962.12,3360.24) 959.34,3357.45 963.51,3353.28 971.46,3360.24 963.51,3367.19 959.34,3363.02 ccw(c962.12,3360.24)
CM_1V8 on TOP "TOP-CM_1V8" (solid, pour order 1251): 857.11,1230.08 ccw(c852.93,1234.25) 857.11,1238.43 854.32,1241.21 845.89,1234.25 854.32,1227.3 857.11,1230.08 ccw(c852.93,1234.25)
CM_1V8 on TOP "TOP-CM_1V8 1" (solid, pour order 1252): 837.62,1238.43 ccw(c841.8,1234.25) 837.62,1230.08 840.4,1227.3 848.84,1234.25 840.4,1241.21 837.62,1238.43 ccw(c841.8,1234.25)
CM_1V8 on TOP "TOP-CM_1V8 2" (solid, pour order 1253): 946.04,1262.05 ccw(c950.22,1257.87) 946.04,1253.7 948.83,1250.92 957.26,1257.87 948.83,1264.83 946.04,1262.05 ccw(c950.22,1257.87)
CM_1V8 on TOP "TOP-CM_1V8 3" (solid, pour order 1254): 1179.94,1241.89 ccw(c1175.76,1246.06) 1179.94,1250.24 1177.15,1253.02 1168.72,1246.06 1177.15,1239.11 1179.94,1241.89 ccw(c1175.76,1246.06)
CM_1V8 on TOP "TOP-CM_1V8 4" (solid, pour order 1255): 1268.88,1226.62 ccw(c1273.05,1222.44) 1268.88,1218.26 1271.66,1215.48 1280.1,1222.44 1271.66,1229.4 1268.88,1226.62 ccw(c1273.05,1222.44)
CAM0_DN0 on TOP "TOP-CAM0_DN0" (solid, pour order 1256): 296.01,688.48 ccw(c297.63,690.1) 299.24,688.48 304.58,693.83 297.63,701.36 290.67,693.83 296.01,688.48 ccw(c297.63,690.1)
CAM0_DN0 on TOP "TOP-CAM0_DN0 1" (solid, pour order 1257): 1313.7,1793.76 ccw(c1313.7,1791.48) 1311.42,1791.48 1311.42,1783.92 1321.66,1783.51 1321.26,1793.76 1313.7,1793.76 ccw(c1313.7,1791.48)
CM_VDAC on TOP "TOP-CM_VDAC" (solid, pour order 1258): 857.11,1182.83 ccw(c852.93,1187.01) 857.11,1191.18 854.32,1193.97 845.89,1187.01 854.32,1180.05 857.11,1182.83 ccw(c852.93,1187.01)
CM_VDAC on TOP "TOP-CM_VDAC 1" (solid, pour order 1259): 1268.88,1179.37 ccw(c1273.05,1175.2) 1268.88,1171.02 1271.66,1168.24 1280.1,1175.2 1271.66,1182.15 1268.88,1179.37 ccw(c1273.05,1175.2)
CM_3V3 on TOP "TOP-CM_3V3" (solid, pour order 1260): 857.11,1135.59 ccw(c852.93,1139.76) 857.11,1143.94 854.32,1146.72 845.89,1139.76 854.32,1132.81 857.11,1135.59 ccw(c852.93,1139.76)
CM_3V3 on TOP "TOP-CM_3V3 1" (solid, pour order 1261): 843.42,1149.61 ccw(c843.42,1143.7) 837.52,1143.7 837.52,1139.76 848.4,1138.72 847.36,1149.61 843.42,1149.61 ccw(c843.42,1143.7)
CM_3V3 on TOP "TOP-CM_3V3 2" (solid, pour order 1262): 946.04,1167.56 ccw(c950.22,1163.39) 946.04,1159.21 948.83,1156.43 957.26,1163.39 948.83,1170.34 946.04,1167.56 ccw(c950.22,1163.39)
CM_3V3 on TOP "TOP-CM_3V3 3" (solid, pour order 1263): 1179.94,1147.4 ccw(c1175.76,1151.58) 1179.94,1155.75 1177.15,1158.53 1168.72,1151.58 1177.15,1144.62 1179.94,1147.4 ccw(c1175.76,1151.58)
CM_3V3 on TOP "TOP-CM_3V3 4" (solid, pour order 1264): 1268.88,1132.13 ccw(c1273.05,1127.95) 1268.88,1123.78 1271.66,1121 1280.1,1127.95 1271.66,1134.91 1268.88,1132.13 ccw(c1273.05,1127.95)
CAM0_DP1 on TOP "TOP-CAM0_DP1" (solid, pour order 1265): 147.79,564.53 ccw(c146.17,566.14) 147.79,567.76 142.44,573.1 134.91,566.14 142.44,559.18 147.79,564.53 ccw(c146.17,566.14)
CAM0_DP1 on TOP "TOP-CAM0_DP1 1" (solid, pour order 1266): 1311.61,1667.41 ccw(c1313.9,1667.41) 1313.9,1665.13 1321.46,1665.13 1321.86,1675.37 1311.61,1674.97 1311.61,1667.41 ccw(c1313.9,1667.41)
GPIO6 on TOP "TOP-GPIO6" (solid, pour order 1267): 984.93,3315.78 ccw(c987.71,3312.99) 984.93,3310.21 989.1,3306.04 997.05,3312.99 989.1,3319.95 984.93,3315.78 ccw(c987.71,3312.99)
DSI0_DN0 on TOP "TOP-DSI0_DN0" (solid, pour order 1268): 142,2569.74 ccw(c139.72,2569.74) 139.72,2572.03 132.16,2572.03 131.76,2561.78 142,2562.18 142,2569.74 ccw(c139.72,2569.74)
DSI0_DN0 on TOP "TOP-DSI0_DN0 1" (solid, pour order 1269): 747.72,2244.91 ccw(c747.72,2247.19) 750,2247.19 750,2254.75 739.75,2255.15 740.16,2244.91 747.72,2244.91 ccw(c747.72,2247.19)
DSI1_DN1 on TOP "TOP-DSI1_DN1" (solid, pour order 1270): 266.76,3339.74 ccw(c266.76,3337.46) 264.48,3337.46 264.48,3329.9 274.72,3329.49 274.32,3339.74 266.76,3339.74 ccw(c266.76,3337.46)
DSI1_DN1 on TOP "TOP-DSI1_DN1 1" (solid, pour order 1271): 1313.64,2008.12 ccw(c1313.64,2005.86) 1311.38,2005.86 1311.38,1998.28 1321.62,1997.88 1321.22,2008.12 1313.64,2008.12 ccw(c1313.64,2005.86)
GPIO27 on TOP "TOP-GPIO27" (solid, pour order 1272): 1142.41,2370.89 ccw(c1145.19,2368.11) 1142.41,2365.33 1146.58,2361.15 1154.53,2368.11 1146.58,2375.07 1142.41,2370.89 ccw(c1145.19,2368.11)
GPIO23 on TOP "TOP-GPIO23" (solid, pour order 1273): 992.8,2512.63 ccw(c995.59,2509.84) 992.8,2507.06 996.98,2502.89 1004.92,2509.84 996.98,2516.8 992.8,2512.63 ccw(c995.59,2509.84)
GPIO19 on TOP "TOP-GPIO19" (solid, pour order 1274): 944.65,2654.36 ccw(c947.44,2651.58) 944.65,2648.79 948.83,2644.62 956.77,2651.58 948.83,2658.53 944.65,2654.36 ccw(c947.44,2651.58)
DSI0_DP0 on TOP "TOP-DSI0_DP0" (solid, pour order 1275): 139.72,2585.46 ccw(c139.72,2587.74) 142,2587.74 142,2595.3 131.76,2595.7 132.16,2585.46 139.72,2585.46 ccw(c139.72,2587.74)
DSI0_DP0 on TOP "TOP-DSI0_DP0 1" (solid, pour order 1276): 750,2229.19 ccw(c747.72,2229.19) 747.72,2231.48 740.16,2231.48 739.75,2221.23 750,2221.63 750,2229.19 ccw(c747.72,2229.19)
GPIO12 on TOP "TOP-GPIO12" (solid, pour order 1277): 971.15,2890.58 ccw(c973.93,2887.8) 971.15,2885.01 975.32,2880.84 983.27,2887.8 975.32,2894.75 971.15,2890.58 ccw(c973.93,2887.8)
GND on GNDT "GNDT-GND" (solid, pour order 1278): 17 vertices, not listed, extent 19.68,19.68 3326.77,4114.17
CD0_SDA on PWRT "PWRT-CD0_SDA" (solid, pour order 1279): 88.58,862.21 ccw(c84.65,862.21) 84.65,866.14 78.74,866.14 78.04,855.6 88.58,856.3 88.58,862.21 ccw(c84.65,862.21)
CD0_SDA on PWRT "PWRT-CD0_SDA 1" (solid, pour order 1280): 66.93,2937.01 ccw(c70.87,2937.01) 70.87,2933.07 76.77,2933.07 77.47,2943.61 66.93,2942.91 66.93,2937.01 ccw(c70.87,2937.01)
CD0_SCL on PWRT "PWRT-CD0_SCL" (solid, pour order 1281): 113.02,830.03 ccw(c110.24,827.25) 107.45,830.03 103.28,825.86 110.24,817.91 117.19,825.86 113.02,830.03 ccw(c110.24,827.25)
CD0_SCL on PWRT "PWRT-CD0_SCL 1" (solid, pour order 1282): 100.39,2893.7 ccw(c100.39,2897.64) 104.33,2897.64 104.33,2903.54 93.79,2904.24 94.49,2893.7 100.39,2893.7 ccw(c100.39,2897.64)
HDMI_SCL on PWRT "PWRT-HDMI_SCL" (solid, pour order 1283): 308.38,2154.7 ccw(c305.59,2157.48) 308.38,2160.26 304.21,2164.44 296.26,2157.48 304.21,2150.52 308.38,2154.7 ccw(c305.59,2157.48)
HDMI_SCL on PWRT "PWRT-HDMI_SCL 1" (solid, pour order 1284): 799.89,1355.15 ccw(c802.67,1352.36) 799.89,1349.58 804.06,1345.41 812.01,1352.36 804.06,1359.32 799.89,1355.15 ccw(c802.67,1352.36)
HDMI_SDA on PWRT "PWRT-HDMI_SDA" (solid, pour order 1285): 308.38,2182.26 ccw(c305.59,2185.04) 308.38,2187.82 304.21,2192 296.26,2185.04 304.21,2178.08 308.38,2182.26 ccw(c305.59,2185.04)
HDMI_SDA on PWRT "PWRT-HDMI_SDA 1" (solid, pour order 1286): 823.51,1378.77 ccw(c826.3,1375.98) 823.51,1373.2 827.68,1369.03 835.63,1375.98 827.68,1382.94 823.51,1378.77 ccw(c826.3,1375.98)
5V on PWRT "PWRT-5V" (solid, pour order 1287): 421 vertices, not listed, extent 19.68,19.68 3326.77,3704.72
1V8 on PWRT "PWRT-1V8" (solid, pour order 1288): 3151.6,377.79 ccw(c3148.82,375) 3146.04,377.79 3141.86,373.61 3148.82,365.67 3155.78,373.61 3151.6,377.79 ccw(c3148.82,375)
1V8 on PWRT "PWRT-1V8 1" (solid, pour order 1289): 410 vertices, not listed, extent 19.68,427.17 3326.77,4114.17
HDMI_CEC on PWRT "PWRT-HDMI_CEC" (solid, pour order 1290): 656.66,2154.22 ccw(c659.45,2157) 662.23,2154.22 666.4,2158.39 659.45,2166.34 652.49,2158.39 656.66,2154.22 ccw(c659.45,2157)
HDMI_CEC on PWRT "PWRT-HDMI_CEC 1" (solid, pour order 1291): 813.81,1410.74 ccw(c811.02,1407.96) 808.24,1410.74 804.07,1406.57 811.02,1398.62 817.98,1406.57 813.81,1410.74 ccw(c811.02,1407.96)
H5V on PWRT "PWRT-H5V" (solid, pour order 1292): 289.37,2220.47 ccw(c283.47,2220.47) 283.47,2226.38 279.53,2226.38 278.48,2215.49 289.37,2216.53 289.37,2220.47 ccw(c283.47,2220.47)
H5V on PWRT "PWRT-H5V 1" (solid, pour order 1293): 581.71,2130.16 ccw(c585.89,2125.98) 581.71,2121.81 584.5,2119.03 592.93,2125.98 584.5,2132.94 581.71,2130.16 ccw(c585.89,2125.98)
H5V on PWRT "PWRT-H5V 2" (solid, pour order 1294): 524.05,2191.04 ccw(c528.23,2195.22) 532.4,2191.04 535.18,2193.83 528.23,2202.26 521.27,2193.83 524.05,2191.04 ccw(c528.23,2195.22)
H5V on PWRT "PWRT-H5V 3" (solid, pour order 1295): 532.4,2210.53 ccw(c528.23,2206.35) 524.05,2210.53 521.27,2207.74 528.23,2199.31 535.18,2207.74 532.4,2210.53 ccw(c528.23,2206.35)
H5V on PWRT "PWRT-H5V 4" (solid, pour order 1296): 532.4,2179.03 ccw(c528.23,2174.86) 524.05,2179.03 521.27,2176.25 528.23,2167.82 535.18,2176.25 532.4,2179.03 ccw(c528.23,2174.86)
H5V on PWRT "PWRT-H5V 5" (solid, pour order 1297): 524.05,2159.55 ccw(c528.23,2163.72) 532.4,2159.55 535.18,2162.34 528.23,2170.77 521.27,2162.34 524.05,2159.55 ccw(c528.23,2163.72)
CD0_SDA on PWRB "PWRB-CD0_SDA" (solid, pour order 1298): 89.87,853.52 ccw(c87.09,856.3) 89.87,859.08 85.7,863.26 77.76,856.3 85.7,849.34 89.87,853.52 ccw(c87.09,856.3)
CD0_SCL on PWRB "PWRB-CD0_SCL" (solid, pour order 1299): 121.37,816.11 ccw(c118.59,818.9) 121.37,821.68 117.2,825.85 109.25,818.9 117.2,811.94 121.37,816.11 ccw(c118.59,818.9)
HDMI_HPD_N_1V8 on PWRB "PWRB-HDMI_HPD_N_1V8" (solid, pour order 1300): 442.91,2401.58 ccw(c438.98,2401.58) 438.98,2405.51 433.07,2405.51 432.37,2394.97 442.91,2395.67 442.91,2401.58 ccw(c438.98,2401.58)
HDMI_HPD_N_1V8 on PWRB "PWRB-HDMI_HPD_N_1V8 1" (solid, pour order 1301): 1328.74,2395.67 ccw(c1332.68,2395.67) 1332.68,2391.73 1338.58,2391.73 1339.28,2402.27 1328.74,2401.58 1328.74,2395.67 ccw(c1332.68,2395.67)
VBUSB on PWRB "PWRB-VBUSB" (solid, pour order 1302): 459.95,416.51 ccw(c457.17,419.29) 459.95,422.08 455.78,426.25 447.84,419.29 455.78,412.34 459.95,416.51 ccw(c457.17,419.29)
CAM0_IO1 on PWRB "PWRB-CAM0_IO1" (solid, pour order 1303): 166.65,794.46 ccw(c163.86,797.24) 166.65,800.03 162.47,804.2 154.53,797.24 162.47,790.29 166.65,794.46 ccw(c163.86,797.24)
CAM0_IO0 on PWRB "PWRB-CAM0_IO0" (solid, pour order 1304): 156.8,753.12 ccw(c154.02,755.9) 156.8,758.69 152.63,762.86 144.68,755.9 152.63,748.95 156.8,753.12 ccw(c154.02,755.9)
3V3 on PWRB "PWRB-3V3" (solid, pour order 1305): 279 vertices, not listed, extent 19.68,19.68 3326.77,4114.17
CD1_SCL on PWRB "PWRB-CD1_SCL" (solid, pour order 1306): 253.94,1687.01 ccw(c253.94,1683.07) 250,1683.07 250,1677.16 260.54,1676.47 259.84,1687.01 253.94,1687.01 ccw(c253.94,1683.07)
CD1_SCL on PWRB "PWRB-CD1_SCL 1" (solid, pour order 1307): 174.52,1542.49 ccw(c171.74,1545.28) 174.52,1548.06 170.35,1552.23 162.4,1545.28 170.35,1538.32 174.52,1542.49 ccw(c171.74,1545.28)
CD1_SCL on PWRB "PWRB-CD1_SCL 2" (solid, pour order 1308): 168.23,3622.05 ccw(c168.23,3625.98) 172.16,3625.98 172.16,3631.89 161.63,3632.59 162.32,3622.05 168.23,3622.05 ccw(c168.23,3625.98)
CAM1_IO0 on PWRB "PWRB-CAM1_IO0" (solid, pour order 1309): 272.94,1483.44 ccw(c270.16,1486.22) 272.94,1489 268.77,1493.18 260.83,1486.22 268.77,1479.26 272.94,1483.44 ccw(c270.16,1486.22)
CD1_SDA on PWRB "PWRB-CD1_SDA" (solid, pour order 1310): 144.99,1562.18 ccw(c142.21,1564.96) 144.99,1567.74 140.82,1571.92 132.87,1564.96 140.82,1558 144.99,1562.18 ccw(c142.21,1564.96)
CD1_SDA on PWRB "PWRB-CD1_SDA 1" (solid, pour order 1311): 136.64,1576.09 ccw(c133.86,1573.31) 131.08,1576.09 126.9,1571.92 133.86,1563.98 140.82,1571.92 136.64,1576.09 ccw(c133.86,1573.31)
CD1_SDA on PWRB "PWRB-CD1_SDA 2" (solid, pour order 1312): 136.98,3640.44 ccw(c139.76,3643.22) 142.55,3640.44 146.72,3644.61 139.76,3652.56 132.81,3644.61 136.98,3640.44 ccw(c139.76,3643.22)
CAM1_IO1 on PWRB "PWRB-CAM1_IO1" (solid, pour order 1313): 170.58,1503.12 ccw(c167.8,1505.91) 170.58,1508.69 166.41,1512.86 158.47,1505.91 166.41,1498.95 170.58,1503.12 ccw(c167.8,1505.91)
CM_VBAT on PWRB "PWRB-CM_VBAT" (solid, pour order 1314): 1287.4,811.02 1185.04,811.02 1185.04,1047.24 838.58,1047.24 838.58,1102.36 948.13,1102.36 948.56,1102.14 ccw(c955.79,1116.14) 963.01,1102.14 963.44,1102.36 1154.48,1102.36 1154.84,1100.81 ccw(c1170.2,1104.33) 1185.55,1100.81 1185.91,1102.36 1287.4,1102.36
CM_1V8 on PWRB "PWRB-CM_1V8" (solid, pour order 1315): 24 vertices, not listed, extent 838.58,811.02 1586.61,1267.72
CM_VDAC on PWRB "PWRB-CM_VDAC" (solid, pour order 1316): 857.11,1182.83 ccw(c852.93,1187.01) 857.11,1191.18 854.32,1193.97 845.89,1187.01 854.32,1180.05 857.11,1182.83 ccw(c852.93,1187.01)
CM_VDAC on PWRB "PWRB-CM_VDAC 1" (solid, pour order 1317): 1268.88,1179.37 ccw(c1273.05,1175.2) 1268.88,1171.02 1271.66,1168.24 1280.1,1175.2 1271.66,1182.15 1268.88,1179.37 ccw(c1273.05,1175.2)
CM_3V3 on PWRB "PWRB-CM_3V3" (solid, pour order 1318): 24 vertices, not listed, extent 838.58,811.02 1405.51,1173.23
VG1 on PWRB "PWRB-VG1" (solid, pour order 1319): 2618.11,3838.58 2814.96,3838.58 2834.65,3818.9 2834.65,1141.73 2814.96,1122.05 2775.59,1122.05 2755.91,1141.73 2755.91,3740.16 2736.22,3759.84 2618.11,3759.84 2598.43,3779.53 2598.43,3818.9
VG0 on PWRB "PWRB-VG0" (solid, pour order 1320): 103 vertices, not listed, extent 2598.43,1122.05 3326.77,4114.17
GND on GNDB "GNDB-GND" (solid, pour order 1321): 17 vertices, not listed, extent 19.68,19.68 3326.77,4114.17
N1357591 on BOTTOM "BOTTOM-N1357591" (solid, pour order 1322): 3151.58,541.34 ccw(c3151.58,537.4) 3147.64,537.4 3147.64,531.5 3158.18,530.8 3157.48,541.34 3151.58,541.34 ccw(c3151.58,537.4)
N1329395 on BOTTOM "BOTTOM-N1329395" (solid, pour order 1323): 438.98,298.15 ccw(c435.04,298.15) 435.04,302.09 429.13,302.09 428.44,291.55 438.98,292.24 438.98,298.15 ccw(c435.04,298.15)
N1329395 on BOTTOM "BOTTOM-N1329395 1" (solid, pour order 1324): 423.23,302.09 ccw(c423.23,298.15) 419.29,298.15 419.29,292.24 429.83,291.55 429.13,302.09 423.23,302.09 ccw(c423.23,298.15)
N1329395 on BOTTOM "BOTTOM-N1329395 2" (solid, pour order 1325): 1068.9,862.21 ccw(c1068.9,858.27) 1064.96,858.27 1064.96,852.36 1075.5,851.66 1074.8,862.21 1068.9,862.21 ccw(c1068.9,858.27)
DSI1_DP0 on BOTTOM "BOTTOM-DSI1_DP0" (solid, pour order 1326): 605.98,3294.12 ccw(c605.98,3296.4) 608.27,3296.4 608.27,3303.96 598.02,3304.37 598.42,3294.12 605.98,3294.12 ccw(c605.98,3296.4)
DSI1_DP0 on BOTTOM "BOTTOM-DSI1_DP0 1" (solid, pour order 1327): 1308.92,2314.36 ccw(c1310.53,2312.74) 1308.92,2311.13 1314.26,2305.79 1321.79,2312.74 1314.26,2319.7 1308.92,2314.36 ccw(c1310.53,2312.74)
DSI0_DN1 on BOTTOM "BOTTOM-DSI0_DN1" (solid, pour order 1328): 276.72,2521.37 ccw(c275.11,2522.98) 276.72,2524.6 271.38,2529.94 263.85,2522.98 271.38,2516.02 276.72,2521.37 ccw(c275.11,2522.98)
DSI0_DN1 on BOTTOM "BOTTOM-DSI0_DN1 1" (solid, pour order 1329): 730.32,2318.05 ccw(c732.6,2318.05) 732.6,2315.77 740.16,2315.77 740.56,2326.02 730.32,2325.61 730.32,2318.05 ccw(c732.6,2318.05)
N1203318 on BOTTOM "BOTTOM-N1203318" (solid, pour order 1330): 2074.56,120.18 ccw(c2078.74,124.35) 2082.92,120.18 2085.7,122.97 2078.74,131.4 2071.78,122.97 2074.56,120.18 ccw(c2078.74,124.35)
N1195355 on BOTTOM "BOTTOM-N1195355" (solid, pour order 1331): 1872.15,134.1 ccw(c1876.32,129.92) 1872.15,125.74 1874.93,122.97 1883.37,129.92 1874.93,136.88 1872.15,134.1 ccw(c1876.32,129.92)
GND on BOTTOM "BOTTOM-GND" (solid, pour order 1332): 2604.48,814.97 cw(c2604.48,818.97) 2602.22,822.26 ccw(c2579.92,854.72) 2600.57,888.26 cw(c2602.66,891.66) 2602.66,895.66 2657.18,895.66 cw(c2657.18,891.66) 2659.28,888.26 ccw(c2679.92,854.72) 2657.63,822.26 cw(c2655.36,818.97) 2655.36,814.97 2604.48,814.97 cw(c2604.48,818.97)
GND on BOTTOM "BOTTOM-GND 1" (solid, pour order 1333): 2599.1,1011.82 cw(c2599.11,1015.82) 2597.34,1019.4 ccw(c2579.92,1054.73) 2606.68,1083.61 cw(c2609.4,1086.54) 2609.4,1090.54 2650.44,1090.54 cw(c2650.44,1086.54) 2653.16,1083.61 ccw(c2679.92,1054.73) 2662.51,1019.4 cw(c2660.74,1015.82) 2660.74,1011.82 2599.1,1011.82 cw(c2599.11,1015.82)
GND on BOTTOM "BOTTOM-GND 2" (solid, pour order 1334): 2652.24,1417.33 2607.61,1417.33 cw(c2607.61,1421.33) 2605.05,1424.41 ccw(c2579.92,1454.72) 2599.98,1488.61 cw(c2602.01,1492.06) 2602.01,1496.05 2657.83,1496.05 cw(c2657.83,1492.06) 2659.87,1488.61 ccw(c2679.92,1454.72) 2654.79,1424.41 cw(c2652.24,1421.33)
GND on BOTTOM "BOTTOM-GND 3" (solid, pour order 1335): 2603.29,1614.18 cw(c2603.29,1618.18) 2601.14,1621.55 ccw(c2579.92,1654.72) 2601.68,1687.54 cw(c2603.9,1690.87) 2603.9,1694.87 2655.95,1694.87 cw(c2655.95,1690.87) 2658.16,1687.54 ccw(c2679.92,1654.72) 2658.7,1621.55 cw(c2656.55,1618.18) 2656.55,1614.18 2603.29,1614.18 cw(c2603.29,1618.18)
GND on BOTTOM "BOTTOM-GND 4" (solid, pour order 1336): 2601.34,1813 cw(c2601.33,1817) 2599.36,1820.48 ccw(c2579.92,1854.72) 2600.57,1888.26 cw(c2602.66,1891.66) 2602.66,1895.66 2657.18,1895.66 cw(c2657.18,1891.66) 2659.28,1888.26 ccw(c2679.92,1854.73) 2660.48,1820.48 cw(c2658.51,1817) 2658.51,1813 2601.34,1813 cw(c2601.33,1817)
GND on BOTTOM "BOTTOM-GND 5" (solid, pour order 1337): 2654.25,2015.76 2605.59,2015.76 cw(c2605.59,2019.76) 2603.22,2022.98 ccw(c2579.92,2054.72) 2599.36,2088.97 cw(c2601.33,2092.45) 2601.34,2096.45 2658.51,2096.45 cw(c2658.51,2092.45) 2660.48,2088.97 ccw(c2679.92,2054.72) 2656.62,2022.98 cw(c2654.25,2019.76)
GND on BOTTOM "BOTTOM-GND 6" (solid, pour order 1338): 2603.9,2214.58 cw(c2603.9,2218.58) 2601.68,2221.91 ccw(c2579.92,2254.73) 2598.04,2289.68 cw(c2599.88,2293.24) 2599.88,2297.24 2659.96,2297.24 cw(c2659.96,2293.24) 2661.8,2289.68 ccw(c2679.92,2254.73) 2658.16,2221.91 cw(c2655.95,2218.58) 2655.95,2214.58 2603.9,2214.58 cw(c2603.9,2218.58)
GND on BOTTOM "BOTTOM-GND 7" (solid, pour order 1339): 2654.8,2415.36 2605.04,2415.36 cw(c2605.05,2419.36) 2602.73,2422.62 ccw(c2579.92,2454.72) 2599.98,2488.61 cw(c2602.01,2492.06) 2602.01,2496.05 2657.83,2496.05 cw(c2657.83,2492.06) 2659.87,2488.61 ccw(c2679.92,2454.72) 2657.11,2422.62 cw(c2654.8,2419.36)
GND on BOTTOM "BOTTOM-GND 8" (solid, pour order 1340): 2653.72,2616.15 2606.12,2616.15 cw(c2606.12,2620.15) 2603.7,2623.34 ccw(c2579.92,2654.72) 2601.68,2687.54 cw(c2603.9,2690.87) 2603.9,2694.87 2655.95,2694.87 cw(c2655.95,2690.87) 2658.16,2687.54 ccw(c2679.92,2654.72) 2656.14,2623.34 cw(c2653.73,2620.15)
GND on BOTTOM "BOTTOM-GND 9" (solid, pour order 1341): 2601.34,2813 cw(c2601.33,2817) 2599.36,2820.48 ccw(c2579.92,2854.72) 2600.57,2888.26 cw(c2602.66,2891.66) 2602.66,2895.66 2657.18,2895.66 cw(c2657.18,2891.66) 2659.28,2888.26 ccw(c2679.92,2854.73) 2660.48,2820.48 cw(c2658.51,2817) 2658.51,2813 2601.34,2813 cw(c2601.33,2817)
GND on BOTTOM "BOTTOM-GND 10" (solid, pour order 1342): 2599.1,3011.82 cw(c2599.11,3015.82) 2597.34,3019.41 ccw(c2579.92,3054.72) 2602.22,3087.18 cw(c2604.48,3090.48) 2604.48,3094.48 2655.36,3094.48 cw(c2655.36,3090.48) 2657.63,3087.18 ccw(c2679.92,3054.72) 2662.51,3019.41 cw(c2660.74,3015.82) 2660.74,3011.82 2599.1,3011.82 cw(c2599.11,3015.82)
GND on BOTTOM "BOTTOM-GND 11" (solid, pour order 1343): 2603.9,3214.58 cw(c2603.9,3218.58) 2601.68,3221.91 ccw(c2579.92,3254.73) 2598.04,3289.68 cw(c2599.88,3293.24) 2599.88,3297.24 2659.96,3297.24 cw(c2659.96,3293.24) 2661.8,3289.68 ccw(c2679.92,3254.73) 2658.16,3221.91 cw(c2655.95,3218.58) 2655.95,3214.58 2603.9,3214.58 cw(c2603.9,3218.58)
GND on BOTTOM "BOTTOM-GND 12" (solid, pour order 1344): 2602.01,3413.39 cw(c2602.01,3417.39) 2599.98,3420.84 ccw(c2579.92,3454.72) 2602.73,3486.83 cw(c2605.05,3490.09) 2605.04,3494.09 2654.8,3494.09 cw(c2654.8,3490.09) 2657.11,3486.83 ccw(c2679.92,3454.72) 2659.87,3420.84 cw(c2657.83,3417.39) 2657.83,3413.39 2602.01,3413.39 cw(c2602.01,3417.39)
GND on BOTTOM "BOTTOM-GND 13" (solid, pour order 1345): 63 vertices, not listed, extent 19.68,19.68 3326.77,4114.17
GND on BOTTOM "BOTTOM-GND 14" (solid, pour order 1346): 24 vertices, not listed, extent 989.55,3407.49 1779.52,3490.15
GND on BOTTOM "BOTTOM-GND 15" (solid, pour order 1347): 1305.15,3309.06 1267.86,3309.06 1246.21,3330.71 1263.92,3348.42 1275.45,3348.42 1307.97,3315.89 cw(c1305.14,3313.06)
GND on BOTTOM "BOTTOM-GND 16" (solid, pour order 1348): 2558.51,2813 2519.83,2813 2098.57,3234.26 1234.22,3234.26 cw(c1234.23,3238.26) 1231.4,3241.09 1256.55,3266.24 2133.22,3266.24 2503.8,2895.66 2557.18,2895.66 cw(c2557.18,2891.66) 2559.28,2888.26 ccw(c2579.92,2854.73) 2560.48,2820.48 cw(c2558.51,2817)
GND on BOTTOM "BOTTOM-GND 17" (solid, pour order 1349): 27 vertices, not listed, extent 950.59,1417.33 2561.83,2565.22
GND on BOTTOM "BOTTOM-GND 18" (solid, pour order 1350): 1228.3,3374.01 cw(c1228.3,3378.01) 1225.48,3380.84 1250.14,3405.5 1954.58,3405.5 1979.25,3380.84 cw(c1976.42,3378.01) 1976.42,3374.01 1314.93,3374.01 1314.57,3375.56 ccw(c1299.21,3372.05) 1283.85,3375.56 1283.5,3374.01 1228.3,3374.01 cw(c1228.3,3378.01)
GPIO26 on BOTTOM "BOTTOM-GPIO26" (solid, pour order 1351): 1127.28,2388.95 ccw(c1124.49,2391.73) 1127.28,2394.52 1123.1,2398.69 1115.16,2391.73 1123.1,2384.78 1127.28,2388.95 ccw(c1124.49,2391.73)
GPIO24 on BOTTOM "BOTTOM-GPIO24" (solid, pour order 1352): 1143.7,2452.76 ccw(c1143.7,2456.69) 1147.64,2456.69 1147.64,2462.6 1137.1,2463.3 1137.8,2452.76 1143.7,2452.76 ccw(c1143.7,2456.69)
CAM0_CN on BOTTOM "BOTTOM-CAM0_CN" (solid, pour order 1353): 147.79,592.54 ccw(c146.17,594.15) 147.79,595.77 142.44,601.11 134.91,594.15 142.44,587.2 147.79,592.54 ccw(c146.17,594.15)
